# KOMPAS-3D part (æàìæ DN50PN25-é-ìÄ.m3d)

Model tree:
1. Объединить компоненты:1  (labels: СЕНС DN50PN25-В-НО)

Referenced files in D:\Савин\!СЕНСОР\3D для заказчика\!Новый перечень\СЕНС\6. СЕНС-В-НО\DN50\: СЕНС DN50PN25-В-НО.a3d
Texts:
  СЕНС DN50PN25-В-НО
  ООО НПП Сенсор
